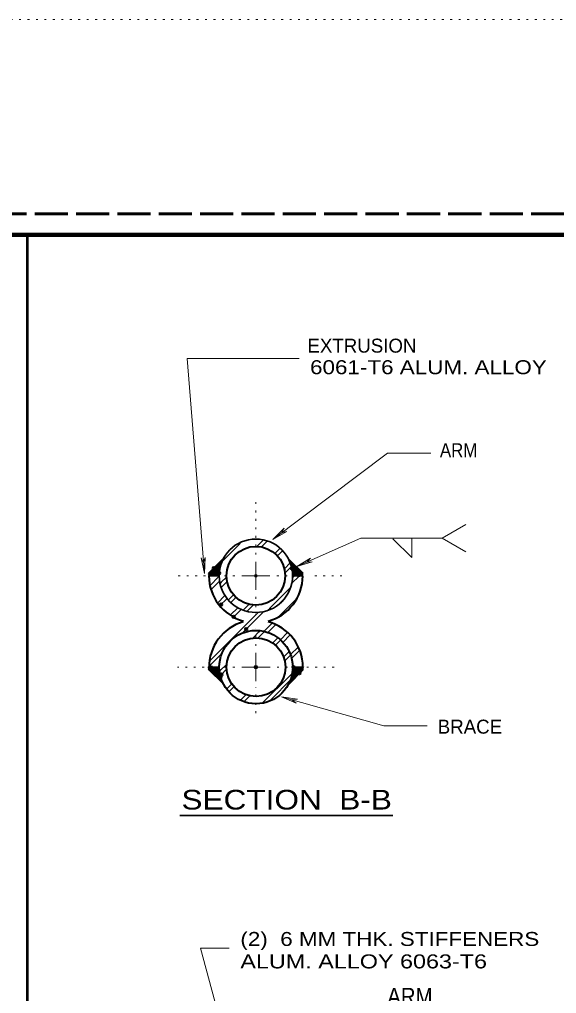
# Model space of a CAD drawing. Extents: x 312583 to 312854, y 144419 to 144597.
# Drawn here: x 312723.1 to 312752.3, y 144543.8 to 144596.8 of the extents above; entities that cross this region are included whole.
import ezdxf
from ezdxf.enums import TextEntityAlignment as Align

# ---------------------------------------------------------------- set-up
doc = ezdxf.new("R2010")
doc.units = 0
doc.header["$LTSCALE"] = 0.3
doc.header["$PDMODE"] = 32
doc.header["$PDSIZE"] = 0.15
doc.linetypes.add('DOTTED', pattern=[1.5, 0.3, -1.2])
doc.linetypes.add('LONG_DASHED', pattern=[7.5, 6, -1.5])
for name, color, linetype, lineweight in [('1', 7, 'Continuous', 35), ('2', 7, 'Continuous', 13), ('62', 7, 'DOTTED', 13), ('63', 7, 'LONG_DASHED', 60)]:
    doc.layers.add(name, color=color, linetype=linetype, lineweight=lineweight)

msp = doc.modelspace()

# ---------------------------------------------------------------- linework, layer by layer
at = {"layer": '1', "lineweight": 53}
msp.add_line((312723.535, 144585.0846), (312723.535, 144513.591), dxfattribs=at)
at = {"layer": '1'}
for p, q in [((312733.4018, 144566.6766), (312734.2681, 144567.5429)), ((312738.5461, 144566.6843), (312737.7411, 144567.4816)), ((312733.4018, 144566.5386), (312733.9691, 144566.5463)), ((312737.9098, 144566.0939), (312738.3621, 144566.5386)), ((312737.9941, 144566.4466), (312738.0861, 144566.5386)), ((312738.5461, 144566.5386), (312738.0094, 144566.5386)), ((312733.4784, 144565.9943), (312733.9691, 144566.4926)), ((312733.5168, 144565.7643), (312734.0151, 144566.2626)), ((312733.8848, 144565.0513), (312734.2988, 144565.4653)), ((312734.0074, 144564.8979), (312734.4138, 144565.3043)), ((312737.1738, 144564.2769), (312738.2318, 144565.3273)), ((312733.4324, 144561.8849), (312736.1004, 144564.5529)), ((312734.5901, 144564.3996), (312735.0118, 144564.8213)), ((312734.7588, 144564.2923), (312735.1958, 144564.7293)), ((312735.2418, 144563.4259), (312736.3918, 144564.5759)), ((312736.4224, 144563.5179), (312736.8671, 144563.9626)), ((312736.6371, 144563.4643), (312737.0741, 144563.8936)), ((312735.8321, 144563.1729), (312736.1541, 144563.5026)), ((312736.1004, 144563.1653), (312736.4454, 144563.5179)), ((312736.1388, 144563.4796), (312736.2154, 144563.5563)), ((312737.3194, 144563.0656), (312737.7028, 144563.4489)), ((312736.9054, 144562.8893), (312737.1354, 144563.1269)), ((312737.0511, 144562.7666), (312737.3348, 144563.0503)), ((312737.1201, 144563.1116), (312737.1814, 144563.1729)), ((312737.4574, 144562.9276), (312737.8254, 144563.3033)), ((312733.3941, 144561.5783), (312734.1454, 144562.3296)), ((312737.4804, 144562.1149), (312737.7488, 144562.3833)), ((312737.7334, 144562.3603), (312737.7948, 144562.4216)), ((312737.8638, 144562.2529), (312738.2778, 144562.6669)), ((312737.9328, 144562.0536), (312738.3774, 144562.4906)), ((312734.0074, 144561.3483), (312734.3984, 144561.7393)), ((312737.5571, 144561.9156), (312737.8714, 144562.2299)), ((312733.3941, 144561.5783), (312733.9614, 144561.5783)), ((312733.3941, 144561.4556), (312734.2144, 144560.6429)), ((312734.0918, 144561.1643), (312734.3831, 144561.4556)), ((312738.5691, 144561.4403), (312737.7334, 144560.5969)), ((312737.8484, 144561.1259), (312737.9558, 144561.2333)), ((312738.5691, 144561.5706), (312738.0018, 144561.5706)), ((312738.5461, 144561.5706), (312738.5691, 144561.6013)), ((312734.0458, 144561.1183), (312734.1148, 144561.1796)), ((312736.3304, 144559.6079), (312737.8791, 144561.1566)), ((312736.8441, 144559.8456), (312737.8484, 144560.8576)), ((312734.3908, 144560.3746), (312734.6821, 144560.6736)), ((312734.5134, 144560.2289), (312734.5671, 144560.2826)), ((312734.5518, 144560.2673), (312734.7894, 144560.5049)), ((312735.1344, 144559.7689), (312735.4411, 144560.0756)), ((312735.3338, 144559.6923), (312735.3951, 144559.7613)), ((312735.3798, 144559.7383), (312735.6558, 144560.0219)), ((312736.7061, 144559.7153), (312736.8671, 144559.8763))]:
    msp.add_line(p, q, dxfattribs=at)
at = {"layer": '1', "lineweight": 40}
for p, q in [((312733.4018, 144566.6689), (312734.2528, 144567.5199)), ((312733.4018, 144566.5769), (312734.1531, 144567.3283)), ((312733.4631, 144566.5463), (312734.0918, 144567.1673)), ((312737.7641, 144567.4356), (312737.7794, 144567.4509)), ((312737.7948, 144567.3666), (312737.8254, 144567.4049)), ((312737.8254, 144567.3053), (312737.8714, 144567.3589)), ((312737.8484, 144567.2363), (312737.9174, 144567.3053)), ((312737.8791, 144567.1749), (312737.9711, 144567.2593)), ((312737.9021, 144567.0983), (312738.0171, 144567.2133)), ((312737.9098, 144567.0216), (312738.0631, 144567.1673)), ((312737.9251, 144566.9373), (312738.1091, 144567.1213)), ((312737.9404, 144566.8606), (312738.1551, 144567.0753)), ((312733.5628, 144566.5463), (312734.0458, 144567.0293)), ((312733.6548, 144566.5463), (312734.0228, 144566.9066)), ((312733.7468, 144566.5463), (312733.9921, 144566.7916)), ((312733.8388, 144566.5463), (312733.9844, 144566.6843)), ((312733.9384, 144566.5463), (312733.9768, 144566.5846)), ((312737.9558, 144566.7839), (312738.2011, 144567.0293)), ((312737.9711, 144566.6996), (312738.2471, 144566.9833)), ((312737.9788, 144566.6153), (312738.3008, 144566.9296)), ((312737.9941, 144566.5386), (312738.3468, 144566.8836)), ((312738.0861, 144566.5386), (312738.3928, 144566.8376)), ((312738.1781, 144566.5386), (312738.4388, 144566.7916)), ((312738.2778, 144566.5386), (312738.4848, 144566.7456)), ((312738.4618, 144566.5386), (312738.5461, 144566.6229)), ((312733.3941, 144561.5016), (312733.4708, 144561.5783)), ((312733.6088, 144561.2409), (312733.9461, 144561.5783)), ((312733.6548, 144561.1949), (312733.9844, 144561.5246)), ((312733.7008, 144561.1489), (312733.9921, 144561.4403)), ((312733.7468, 144561.1029), (312733.9998, 144561.3483)), ((312733.7928, 144561.0569), (312734.0151, 144561.2716)), ((312737.7488, 144560.6353), (312738.5691, 144561.4556)), ((312737.8408, 144560.8193), (312738.5691, 144561.5476)), ((312737.8944, 144560.9649), (312738.5001, 144561.5706)), ((312737.9251, 144561.0876), (312738.4081, 144561.5706)), ((312737.9481, 144561.2103), (312738.3161, 144561.5706)), ((312737.9634, 144561.3176), (312738.2164, 144561.5706)), ((312737.9711, 144561.4249), (312738.1244, 144561.5706)), ((312737.9941, 144561.5399), (312738.0324, 144561.5706)), ((312733.8464, 144561.0033), (312734.0304, 144561.1949)), ((312733.8924, 144560.9573), (312734.0534, 144561.1183)), ((312733.9384, 144560.9113), (312734.0688, 144561.0493)), ((312733.9844, 144560.8653), (312734.0918, 144560.9726)), ((312734.0304, 144560.8193), (312734.1148, 144560.9036)), ((312734.0764, 144560.7733), (312734.1378, 144560.8269)), ((312734.1224, 144560.7273), (312734.1608, 144560.7579)), ((312734.1684, 144560.6813), (312734.1914, 144560.6966))]:
    msp.add_line(p, q, dxfattribs=at)
at = {"layer": '1', "lineweight": 158}
msp.add_lwpolyline([(312616.5, 144423.1446), (312616.5, 144585.0846), (312849, 144585.0846)], dxfattribs=at)
at = {"layer": '1', "lineweight": 40}
for points in [[(312738.3698, 144566.5386), (312738.5308, 144566.6996), (312738.5308, 144566.6996)], [(312733.4171, 144561.4249), (312733.4171, 144561.4326), (312733.5628, 144561.5783)], [(312733.4631, 144561.3789), (312733.4631, 144561.3789), (312733.6624, 144561.5783)], [(312733.5168, 144561.3329), (312733.5168, 144561.3329), (312733.7544, 144561.5783)], [(312733.5628, 144561.2869), (312733.5628, 144561.2869), (312733.8464, 144561.5783)]]:
    msp.add_lwpolyline(points, dxfattribs=at)
at = {"layer": '1'}
msp.add_circle((312735.9797, 144566.5418), 1.9965, dxfattribs=at)
for p in [(312733.6931, 144566.9603), (312733.7391, 144566.9143), (312733.7851, 144566.8606), (312733.8311, 144566.8146), (312733.8771, 144566.7686), (312733.9231, 144566.7226), (312733.9768, 144566.6766), (312737.9328, 144566.9449), (312737.9864, 144566.8989), (312738.0324, 144566.8529), (312738.0784, 144566.8069), (312738.1244, 144566.7609), (312738.1704, 144566.7149), (312738.2164, 144566.6689), (312738.2624, 144566.6153), (312738.3084, 144566.5693), (312734.0918, 144564.9823), (312734.7741, 144564.3076), (312735.4488, 144563.6329), (312733.5474, 144561.5553), (312733.5934, 144561.5093), (312733.6394, 144561.4556), (312733.6854, 144561.4096), (312733.7314, 144561.3636), (312733.7774, 144561.3176), (312733.8234, 144561.2716), (312733.8694, 144561.2256), (312733.9231, 144561.1796), (312733.9691, 144561.1336), (312734.1071, 144561.1796), (312735.9854, 144561.5783), (312738.0248, 144561.5706), (312738.0708, 144561.5246), (312738.1168, 144561.4709), (312738.1628, 144561.4249), (312738.2164, 144561.3789), (312738.2624, 144561.3329), (312738.3084, 144561.2869), (312738.3544, 144561.2409), (312734.0151, 144561.0799), (312734.0611, 144561.0339)]:
    msp.add_point(p, dxfattribs=at)
at = {"layer": '2'}
for p, q in [((312732.2441, 144578.3606), (312733.1794, 144566.6689)), ((312738.3391, 144578.3606), (312732.2441, 144578.3606)), ((312743.1461, 144573.2009), (312736.8978, 144568.5166)), ((312745.4998, 144573.2009), (312743.1461, 144573.2009)), ((312746.1208, 144568.5779), (312747.4011, 144569.3216)), ((312736.8978, 144568.5166), (312737.5264, 144569.1223)), ((312736.8978, 144568.5166), (312737.6568, 144568.9536)), ((312737.5264, 144569.1223), (312737.3731, 144568.8693)), ((312737.6568, 144568.9536), (312737.3731, 144568.8693)), ((312743.4374, 144568.5473), (312744.4571, 144567.5276)), ((312744.4571, 144568.5779), (312744.4571, 144567.5276)), ((312746.1208, 144568.5779), (312747.4011, 144567.8419)), ((312733.0031, 144567.5199), (312733.1334, 144567.2593)), ((312733.1794, 144566.6689), (312733.0031, 144567.5199)), ((312733.2178, 144567.5429), (312733.1334, 144567.2593)), ((312733.1794, 144566.6689), (312733.2178, 144567.5429)), ((312735.9778, 144566.5386), (312735.9778, 144567.3053)), ((312738.2088, 144567.0446), (312738.9524, 144567.4893)), ((312738.2088, 144567.0446), (312739.0444, 144567.2899)), ((312738.9524, 144567.4893), (312738.7454, 144567.2823)), ((312739.0444, 144567.2899), (312738.7454, 144567.2823)), ((312735.9778, 144566.5386), (312735.2111, 144566.5386)), ((312735.9778, 144566.5386), (312735.9778, 144565.7719)), ((312735.9778, 144566.5386), (312736.7444, 144566.5386)), ((312735.9854, 144561.5783), (312735.9854, 144562.3449)), ((312735.9854, 144561.5783), (312735.2188, 144561.5783)), ((312735.9854, 144561.5783), (312735.9854, 144560.8116)), ((312735.9854, 144561.5783), (312736.7521, 144561.5783)), ((312742.9468, 144558.3889), (312737.3731, 144559.9606)), ((312737.3731, 144559.9606), (312738.1781, 144559.6233)), ((312737.3731, 144559.9606), (312738.2394, 144559.8303)), ((312738.2394, 144559.8303), (312737.9404, 144559.7996)), ((312738.1781, 144559.6233), (312737.9404, 144559.7996)), ((312745.2928, 144558.3889), (312742.9468, 144558.3889))]:
    msp.add_line(p, q, dxfattribs=at)
at = {"layer": '2', "linetype": 'DOTTED'}
for p, q in [((312735.9778, 144567.6886), (312735.9778, 144570.7093)), ((312733.2408, 144566.5386), (312731.6154, 144566.5386)), ((312734.8278, 144566.5386), (312733.4018, 144566.5386)), ((312737.1278, 144566.5386), (312738.3928, 144566.5386)), ((312739.1901, 144566.5386), (312740.6544, 144566.5386)), ((312735.9778, 144565.3886), (312735.9778, 144564.4456)), ((312735.9854, 144562.7283), (312735.9854, 144563.6483)), ((312733.1641, 144561.5783), (312731.7151, 144561.5783)), ((312734.8354, 144561.5783), (312733.3941, 144561.5783)), ((312737.1354, 144561.5783), (312738.5691, 144561.5783)), ((312738.7531, 144561.5783), (312740.4781, 144561.5783)), ((312735.9854, 144559.0713), (312735.9854, 144560.4589))]:
    msp.add_line(p, q, dxfattribs=at)
at = {"layer": '2', "lineweight": 35}
for p, q in [((312734.1454, 144567.3206), (312735.0654, 144568.2406)), ((312735.0271, 144568.2099), (312735.2034, 144568.3786)), ((312736.0468, 144568.1486), (312736.3994, 144568.4936)), ((312736.2768, 144568.1026), (312736.5681, 144568.3939)), ((312736.5451, 144568.3709), (312736.6141, 144568.4323)), ((312737.0128, 144567.7576), (312737.2964, 144568.0413)), ((312737.1508, 144567.6196), (312737.3961, 144567.8649)), ((312737.5341, 144566.9143), (312737.8484, 144567.2363)), ((312737.5724, 144566.6919), (312737.8714, 144566.9833)), ((312737.8484, 144566.9603), (312737.9174, 144567.0293)), ((312734.0304, 144566.1246), (312734.0994, 144566.1936)), ((312734.0841, 144565.9099), (312734.4138, 144566.2319)), ((312734.0918, 144566.1859), (312734.3754, 144566.4696)), ((312734.5134, 144565.2583), (312734.7664, 144565.5036)), ((312736.7291, 144564.7599), (312737.8714, 144565.9023)), ((312734.4828, 144565.2199), (312734.5441, 144565.2813)), ((312734.6131, 144565.0819), (312734.8968, 144565.3656)), ((312735.3261, 144564.7139), (312735.6098, 144564.9976)), ((312735.4948, 144564.6066), (312735.8398, 144564.9516)), ((312737.2198, 144564.9746), (312737.5418, 144565.3043)), ((312735.2878, 144564.6679), (312735.3491, 144564.7293)), ((312736.6218, 144564.6526), (312736.7751, 144564.8059)), ((312731.8487, 144553.5053), (312743.4374, 144553.5053))]:
    msp.add_line(p, q, dxfattribs=at)
at = {"layer": '2'}
for points in [[(312746.1208, 144568.5779), (312741.6894, 144568.5779), (312738.2088, 144567.0446)], [(312734.5364, 144546.2986), (312732.9724, 144546.2986), (312734.8124, 144539.4446)]]:
    msp.add_lwpolyline(points, dxfattribs=at)
at = {"layer": '2', "lineweight": 35}
msp.add_lwpolyline([(312737.3808, 144567.8496), (312737.4344, 144567.9033), (312737.4421, 144567.9109)], dxfattribs=at)
at = {"layer": '2', "lineweight": 40}
for centre, radius in [((312735.9797, 144566.5418), 1.5972), ((312735.988, 144561.5744), 1.9965), ((312735.988, 144561.5744), 1.5972)]:
    msp.add_circle(centre, radius, dxfattribs=at)
for centre, start, end in [((312735.9797, 144566.5418), 179.98549, 254.57126), ((312735.9797, 144566.5418), 285.12884, 359.64884), ((312735.988, 144561.5744), 105.6477, 180.9673), ((312735.988, 144561.5744), 0.19598, 75.10521)]:
    msp.add_arc(centre, 2.5556, start, end, dxfattribs=at)
at = {"layer": '2'}
msp.add_point((312735.9778, 144566.5386), dxfattribs=at)
at = {"layer": '62'}
msp.add_line((312601.2, 144596.7846), (312853.5, 144596.7846), dxfattribs=at)
at = {"layer": '63'}
msp.add_line((312851.75, 144586.2246), (312583.526, 144586.2246), dxfattribs=at)

# ---------------------------------------------------------------- texts
at = {"layer": '2'}
for s, p in [('EXTRUSION', (312738.7872, 144578.6712)), ('BRACE', (312745.8753, 144557.9577))]:
    msp.add_text(s, height=0.76, dxfattribs=at).set_placement(p)
for s, height, width, p in [('6061-T6 ALUM. ALLOY', 0.76, 1.2, (312738.9286, 144577.5)), ('ARM', 0.76, 0.9, (312745.9944, 144572.9863)), ('(2)  6 MM THK. STIFFENERS', 0.76, 1.2, (312735.1378, 144546.4155)), ('ALUM. ALLOY 6063-T6', 0.76, 1.25, (312735.1378, 144545.1955)), ('ARM', 0.92, 0.9, (312743.1308, 144543.2166))]:
    msp.add_text(s, height=height, dxfattribs=dict(at, width=width)).set_placement(p)
at = {"layer": '2', "width": 1.2}
msp.add_text('SECTION  B-B', height=1.07, dxfattribs=at).set_placement((312737.6571, 144553.8318), align=Align.CENTER)

doc.saveas('drawing.dxf')
